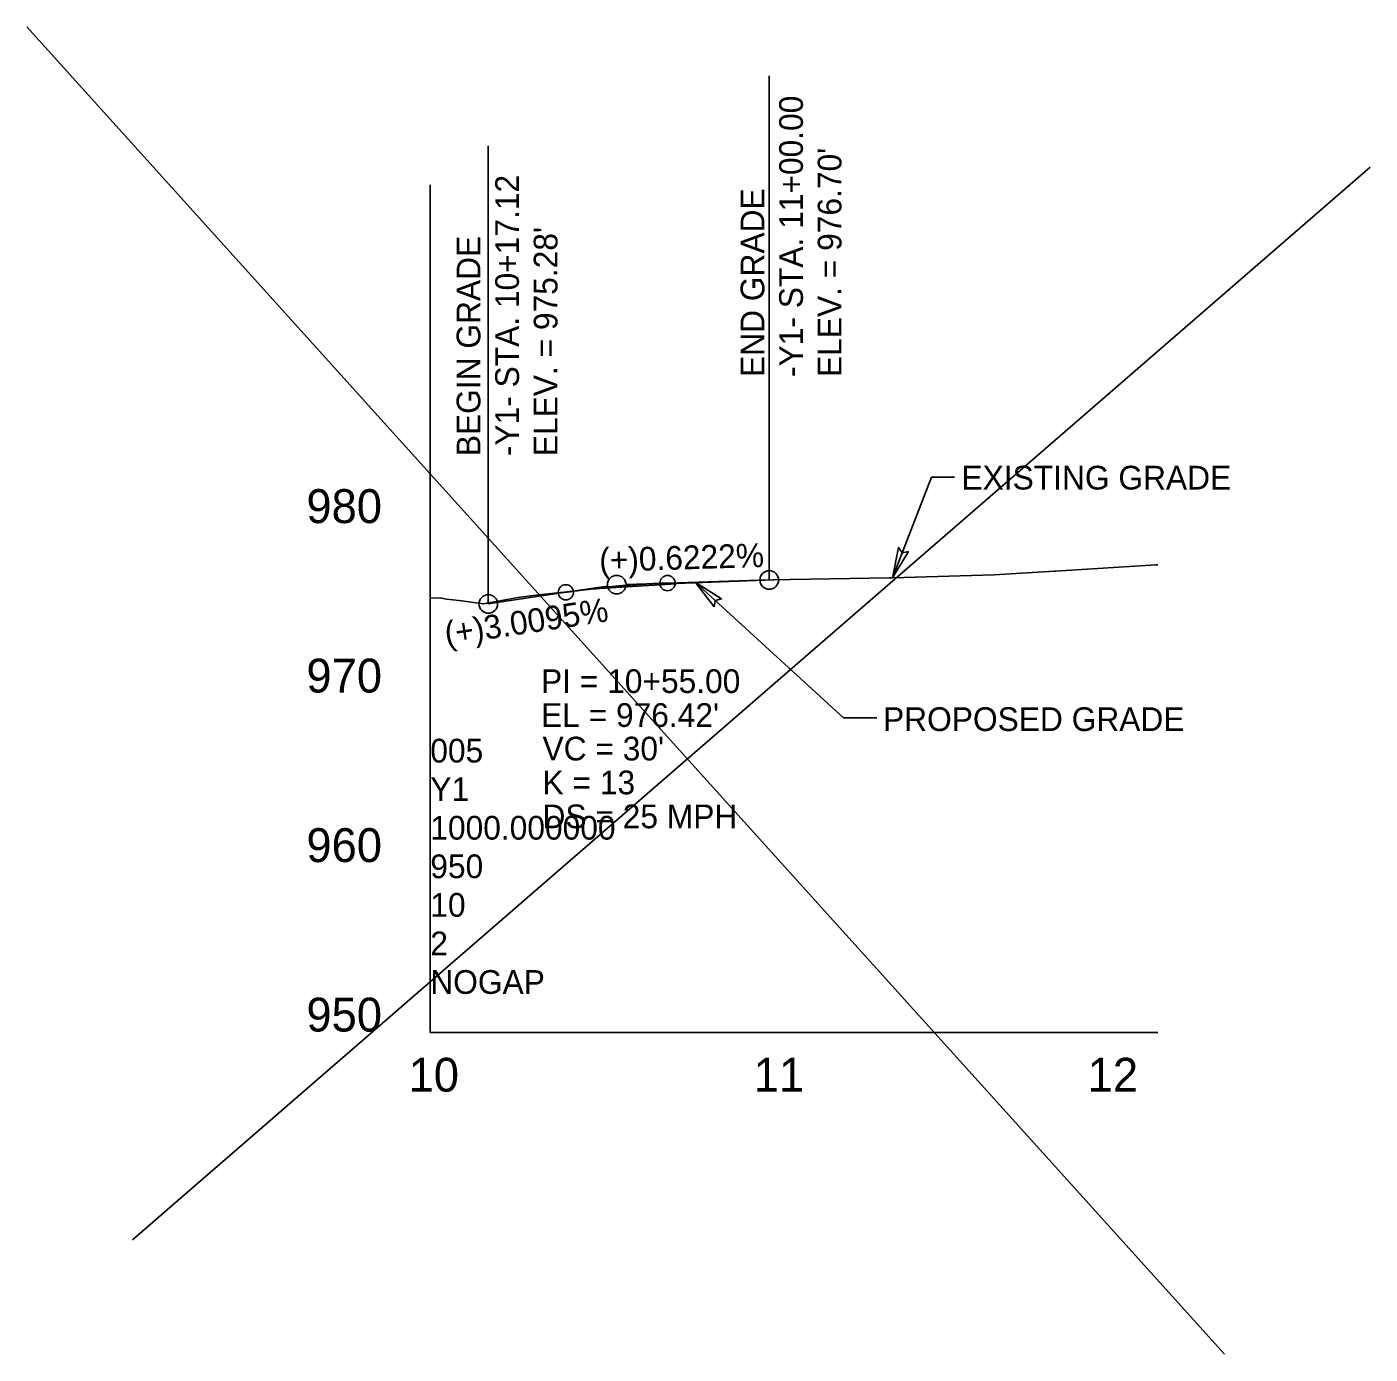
# Model space of a CAD drawing. Extents: x 1615624 to 1632571, y 894455 to 913418.
# Drawn here: x 1624253.5 to 1624649.8, y 897556.1 to 897947.7 of the extents above; entities that cross this region are included whole.
import ezdxf

# ---------------------------------------------------------------- set-up
doc = ezdxf.new("R2010")
doc.units = 0
for name, color, linetype in [('Exist Profile Cell', 7, 'Continuous'), ('Exist Vertical Profile Ground Line', 7, 'Continuous'), ('Exist Vertical Profile Horizontal Axis Label Major', 7, 'Continuous'), ('Exist Vertical Profile Vertical Axis Label', 7, 'Continuous'), ('Prop Terminator CELL', 7, 'Continuous'), ('Prop Vertical Profile Curve Label', 7, 'Continuous'), ('Prop Vertical Profile Grade', 7, 'Continuous'), ('Prop Vertical Profile Grade Label', 7, 'Continuous'), ('Prop VPI Label', 7, 'Continuous')]:
    doc.layers.add(name, color=color, linetype=linetype)

msp = doc.modelspace()

# ---------------------------------------------------------------- linework, layer by layer
at = {"layer": 'Exist Profile Cell'}
for q in [(1624372.54, 897901.02), (1624587.24, 897651.02), (1624372.54, 897651.02)]:
    msp.add_line((1624372.54, 897651.02), q, dxfattribs=at)
at = {"layer": 'Exist Vertical Profile Ground Line'}
msp.add_lwpolyline([(1624372.54, 897779.25), (1624375.7, 897779.14), (1624375.88, 897779.13), (1624377.37, 897778.85), (1624381.03, 897778.43), (1624388.12, 897777.49), (1624398.51, 897779.28), (1624402.24, 897779.85), (1624402.93, 897779.92), (1624420.87, 897781.88), (1624421.43, 897781.92), (1624422.53, 897781.95), (1624445.1, 897783.39), (1624445.23, 897783.4), (1624473.75, 897784.54), (1624473.87, 897784.55), (1624474, 897784.54), (1624478.73, 897784.62), (1624478.82, 897784.62), (1624507.92, 897785.07), (1624508.74, 897785.09), (1624508.92, 897785.09), (1624538.92, 897786.01), (1624556.72, 897787.1), (1624556.99, 897787.12), (1624586.65, 897788.94), (1624586.88, 897788.96), (1624587.23, 897788.92)], dxfattribs=at)
at = {"layer": 'Prop Terminator CELL'}
for points in [[(1624513.63, 897792.92), (1624508.92, 897785.09), (1624510.71, 897794.11), (1624511.78, 897792.46)], [(1624456.31, 897776.59), (1624450.72, 897783.82), (1624458.48, 897778.88), (1624456.55, 897778.48)]]:
    msp.add_lwpolyline(points, close=True, dxfattribs=at)
at = {"layer": 'Prop Vertical Profile Curve Label'}
for centre in [(1624412.54, 897780.85), (1624442.54, 897783.56)]:
    msp.add_circle(centre, 2.25, dxfattribs=at)
at = {"layer": 'Prop Vertical Profile Grade'}
for p, q in [((1624442.54, 897783.56), (1624472.54, 897784.49)), ((1624389.66, 897777.42), (1624412.54, 897780.85))]:
    msp.add_line(p, q, dxfattribs=at)
msp.add_spline([(1624412.54, 897780.85), (1624413.14, 897780.94), (1624413.74, 897781.03), (1624414.34, 897781.11), (1624414.94, 897781.2), (1624415.54, 897781.28), (1624416.14, 897781.36), (1624416.74, 897781.44), (1624417.34, 897781.52), (1624417.94, 897781.6), (1624418.54, 897781.68), (1624419.14, 897781.75), (1624419.74, 897781.83), (1624420.34, 897781.9), (1624420.94, 897781.97), (1624421.54, 897782.04), (1624422.14, 897782.11), (1624422.74, 897782.17), (1624423.34, 897782.24), (1624423.94, 897782.3), (1624424.54, 897782.36), (1624425.14, 897782.42), (1624425.74, 897782.48), (1624426.34, 897782.54), (1624426.94, 897782.6), (1624427.54, 897782.65), (1624428.14, 897782.71), (1624428.74, 897782.76), (1624429.34, 897782.81), (1624429.94, 897782.86), (1624430.54, 897782.91), (1624431.14, 897782.95), (1624431.74, 897783), (1624432.34, 897783.04), (1624432.94, 897783.08), (1624433.54, 897783.12), (1624434.14, 897783.16), (1624434.74, 897783.2), (1624435.34, 897783.24), (1624435.94, 897783.27), (1624436.54, 897783.31), (1624437.14, 897783.34), (1624437.74, 897783.37), (1624438.34, 897783.4), (1624438.94, 897783.43), (1624439.54, 897783.45), (1624440.14, 897783.48), (1624440.74, 897783.5), (1624441.34, 897783.52), (1624441.94, 897783.54), (1624442.54, 897783.56)], degree=3, dxfattribs=at)
at = {"layer": 'Prop Vertical Profile Grade Label'}
for p, q in [((1624472.54, 897784.49), (1624472.54, 897933.17)), ((1624389.66, 897777.42), (1624389.66, 897912.6)), ((1624508.92, 897785.09), (1624520.46, 897814.81)), ((1624520.46, 897814.81), (1624527.24, 897814.81)), ((1624494.43, 897743.78), (1624450.72, 897783.82)), ((1624504.28, 897743.78), (1624494.43, 897743.78))]:
    msp.add_line(p, q, dxfattribs=at)
at = {"layer": 'Prop VPI Label'}
for p, q in [((1624606.84, 897556.11), (1624253.51, 897947.65)), ((1624284.71, 897589.86), (1624649.84, 897906.31)), ((1624442.54, 897783.56), (1624430.29, 897783.18)), ((1624412.54, 897780.85), (1624424.82, 897782.69))]:
    msp.add_line(p, q, dxfattribs=at)
for centre in [(1624472.54, 897784.49), (1624427.54, 897783.1), (1624389.66, 897777.42)]:
    msp.add_circle(centre, 2.75, dxfattribs=at)

# ---------------------------------------------------------------- texts
at = {"layer": 'Exist Profile Cell'}
for s, p in [('005', (1624372.54, 897730.64)), ('Y1', (1624372.54, 897719.27)), ('1000.000000', (1624372.54, 897707.89)), ('950', (1624372.54, 897696.52)), ('10', (1624372.54, 897685.14)), ('2', (1624372.54, 897673.77)), ('NOGAP', (1624372.54, 897662.39))]:
    msp.add_text(s, height=7, dxfattribs=at).set_placement(p)
at = {"layer": 'Exist Vertical Profile Horizontal Axis Label Major'}
for s, p in [('10', (1624366.13, 897633.52)), ('11', (1624467.97, 897633.52)), ('12', (1624566.51, 897633.52))]:
    msp.add_text(s, height=10, dxfattribs=at).set_placement(p)
at = {"layer": 'Exist Vertical Profile Vertical Axis Label'}
for s, p in [('980', (1624335.98, 897801.27)), ('970', (1624335.98, 897751.27)), ('960', (1624335.98, 897701.27)), ('950', (1624335.98, 897651.27))]:
    msp.add_text(s, height=10, dxfattribs=at).set_placement(p)
at = {"layer": 'Prop Vertical Profile Grade Label'}
for s, p in [('EXISTING GRADE', (1624529.27, 897811.17)), ('PROPOSED GRADE', (1624506.12, 897739.93))]:
    msp.add_text(s, height=7, dxfattribs=at).set_placement(p)
for s, rotation, p in [('(+)0.6222%', 1.775, (1624422.48, 897786.83)), ('(+)3.0095%', 8.5308, (1624377.31, 897765.14))]:
    msp.add_text(s, height=7, rotation=rotation, dxfattribs=at).set_placement(p)
at = {"layer": 'Prop VPI Label'}
for s, p in [('-Y1- STA. 11+00.00', (1624482.48, 897844.37)), ("ELEV. = 976.70'", (1624493.86, 897844.37)), ('-Y1- STA. 10+17.12', (1624398.7, 897821)), ('END GRADE', (1624471.11, 897844.37)), ("ELEV. = 975.28'", (1624410.07, 897821)), ('BEGIN GRADE', (1624387.32, 897821))]:
    msp.add_text(s, height=7, rotation=90, dxfattribs=at).set_placement(p)
for s, p in [('PI = 10+55.00', (1624405.21, 897751.14)), ("EL = 976.42'", (1624405.21, 897741.14)), ("VC = 30'", (1624405.65, 897731.25)), ('K = 13', (1624405.65, 897721.25)), ('DS = 25 MPH', (1624405.65, 897711.25))]:
    msp.add_text(s, height=7, dxfattribs=at).set_placement(p)

doc.saveas('drawing.dxf')
